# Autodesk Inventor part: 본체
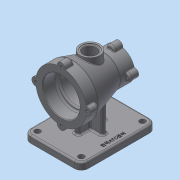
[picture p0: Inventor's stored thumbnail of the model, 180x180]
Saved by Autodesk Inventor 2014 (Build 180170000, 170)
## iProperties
Created: 2020-12
Part Number: 본체
Material: 일반
Document SubType Name: Modeling
Designer: net
Density: 1 g/cm^3
Appearance: 기본값
Author: net
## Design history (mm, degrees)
sketch "스케치1"
  geometry: L1 (-50, -65)-(50, -65); L2 (50, -65)-(50, 65); L3 (50, 65)-(-50, 65); L4 (-50, 65)-(-50, -65); L5 (-50, -65)-(50, 65); L6 (50, -65)-(-50, 65); L7 (4, 24)-(-4, 24); L8 (-4, 24)-(-4, 4); L9 (-4, 4)-(-25, 4); L10 (-25, 4)-(-25, -4); L11 (-25, -4)-(-4, -4); L12 (-4, -4)-(-4, -24); L13 (-4, -24)-(4, -24); L14 (4, -24)-(4, -4); L15 (4, -4)-(25, -4); L16 (25, -4)-(25, 4); L17 (25, 4)-(4, 4); L18 (4, 4)-(4, 24); 5 further points
  constraints: 36 end point, 6 midpoint, 6 parallel, 5 perpendicular, 4 horizontal, 3 equal length, 3 horizontal alignment, 3 vertical alignment, 1 vertical
  dimensions: "d1" = 130 distance of L1.end L2.end; "d2" = 100 distance of L2.end L3.end; "d3" = 8 distance of L15.end L16.end; "d4" = 48 distance between parallel lines of L13 L7; "d5" = 50 distance between parallel lines of L16 L10
extrude "돌출1" new body sketch "스케치1" distance "d6" = 12; taper "d7" = 0 deg
extrude "돌출2" join sketch "스케치1" distance "d8" = 82; taper "d9" = 0 deg
sketch "스케치2"
  geometry: L1 (24, 82)-(4, 82) reference; L2 (-4, 82)-(-24, 82) reference; L3 (4, 82)-(-4, 82) reference; L4 (-50, 82)-(50, 82); L5 (-50, 82)-(-50, 126); L6 (-50, 126)-(-30, 126); L7 (-30, 126)-(25, 109.5); L8 (25, 109.5)-(50, 109.5); L9 (50, 109.5)-(50, 82); L10 (-50, 114)-(-27, 114); L11 (-27, 114)-(-27, 108); L12 (-27, 108)-(20, 108); L13 (20, 108)-(20, 102); L14 (20, 102)-(50, 102); 2 further points
  constraints: 22 end point, 5 perpendicular, 4 parallel, 2 midpoint, 2 point on line, 1 horizontal
  dimensions: "d10" = 100 distance of L4.start L4.end; "d11" = 20 distance of L5.end L6.end; "d12" = 88 diameter of L6 L4; "d13" = 55 diameter of L8 L4; "d14" = 40 diameter of L14 L4; "d15" = 52 diameter of L12 L4; "d16" = 64 diameter of L10 L4; "d17" = 23 distance of L10.start L10.end; "d18" = 47 distance of L11.end L12.end; "d95" = 25 distance from line of L7.end L9
revolve "회전1" stored, may be unused: angle "d19" = 90 deg
revolve "회전2" stored, may be unused: angle "d20" = 90 deg
sketch "스케치3"
  geometry: C1 r 32 at (0, 0) reference; C2 r 7 at (0, 44); 2 further points
  constraints: 2 vertical alignment, 1 centre point, 1 other
  dimensions: "d21" = 14 diameter of C2
extrude "돌출3" join sketch "스케치3" distance "d22" = 15; taper "d23" = 0 deg
sketch "스케치4"
  geometry: A1 r 7 centre (0, 0) between (6.978, -0.557) and (-6.978, -0.557) reference; 1 further point
hole "구멍1" sketch "스케치4" at (0, 0) diameter "d24" = 4.134; stored, may be unused: countersink angle "d28" = 90 deg, drill point angle "d30" = 118 deg; dims "d25" = 9, "d26" = 4, "d27" = 2, "d29" = 11
sketch "스케치5"
  geometry: C1 r 20 at (0, 0) reference; C2 r 7 at (0, -27.5); 2 further points
  constraints: 2 vertical alignment, 1 centre point, 1 other
  dimensions: "d34" = 14 diameter of C2
extrude "돌출4" join sketch "스케치5" distance "d35" = 15; taper "d36" = 0 deg
sketch "스케치6"
  geometry: A1 r 7 centre (0, 0) between (-6.943, 0.891) and (6.943, 0.891) reference; 1 further point
hole "구멍2" sketch "스케치6" at (0, 0) diameter "d37" = 4.134; stored, may be unused: countersink angle "d41" = 90 deg, drill point angle "d43" = 118 deg; dims "d38" = 9, "d39" = 4, "d40" = 2, "d42" = 11
sketch "스케치7"
  geometry: L1 (-30, 126)-(25, 109.5) reference; L2 (-50, 125.443)-(-50, 133) reference; L3 (0, 111)-(0, 127); L4 (0, 127)-(-17, 127); L5 (-17, 127)-(-17, 111); L6 (-17, 111)-(0, 111); L7 (50, 102)-(50, 62) reference; 3 further points
  constraints: 8 end point, 3 perpendicular, 1 midpoint, 1 parallel
  dimensions: "d51" = 50 distance between parallel lines of L2 L3; "d52" = 34 diameter of L5 L3; "d53" = 16 distance of L4.end L5.end; "d54" = 45 distance from line of L4 point (50, 82)
revolve "회전3" sketch "스케치7" stored, may be unused: angle "d55" = 90 deg
fillet "모깎기2" dims "d56" = 1
hole "구멍3" diameter "d59" = 22; stored, may be unused: countersink angle "d63" = 90 deg, drill point angle "d65" = 118 deg; dims "d57" = 10, "d58" = 10, "d60" = 9, "d61" = 28, "d62" = 1, "d64" = 30
chamfer "모따기1" distance "d66" = 1; stored, may be unused: second distance "d67" = 2, angle "d68" = 45 deg
fillet "모깎기3" dims "d69" = 3
fillet "모깎기4" dims "d70" = 3
fillet "모깎기5" dims "d71" = 3
chamfer "모따기2" distance "d72" = 1; stored, may be unused: second distance "d73" = 2, angle "d74" = 45 deg
fillet "모깎기6" dims "d75" = 12
sketch "스케치8"
  geometry: A1 r 12 centre (-38, 53) between (-38, 65) and (-50, 53) reference; A2 r 12 centre (-38, -53) between (-50, -53) and (-38, -65) reference; A3 r 12 centre (38, -53) between (38, -65) and (50, -53) reference; A4 r 12 centre (38, 53) between (50, 53) and (38, 65) reference; 1 further point
hole "구멍4" sketch "스케치8" at (38, -53), (38, 53), (-38, 53), (-38, -53) diameter "d76" = 10; stored, may be unused: countersink angle "d80" = 90 deg, drill point angle "d82" = 118 deg; dims "d77" = 9, "d78" = 28, "d79" = 1, "d81" = 30
fillet "모깎기7" dims "d83" = 3
fillet "모깎기8" dims "d84" = 3
fillet "모깎기9" dims "d88" = 1
sketch "스케치9"
  geometry: L1 (50, -53)-(50, 53) reference; 2 further points
  constraints: 1 horizontal alignment, 1 other
  dimensions: "d92" = 10 distance from line of L1 point (40, 0)
extrude "돌출5" join sketch "스케치9" distance "d93" = 0.5; taper "d94" = 0 deg
node "솔리드1"
pattern_circular "원형 패턴1" dims angle "d32" = 360 deg
pattern_circular "원형 패턴2" dims angle "d45" = 360 deg
pattern_circular "원형 패턴4" dims angle "d86" = 360 deg
pattern_circular "원형 패턴5" dims angle "d90" = 360 deg
